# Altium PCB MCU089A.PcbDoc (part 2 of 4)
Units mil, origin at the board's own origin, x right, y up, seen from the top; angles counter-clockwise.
Board outline 2300 x 5500 mil, 4 copper layers (Top Signal, GND, PWR, Bottom Signal), stack 61.6 mil thick; 262 components, 208 nets, 964 pads, 377 vias.
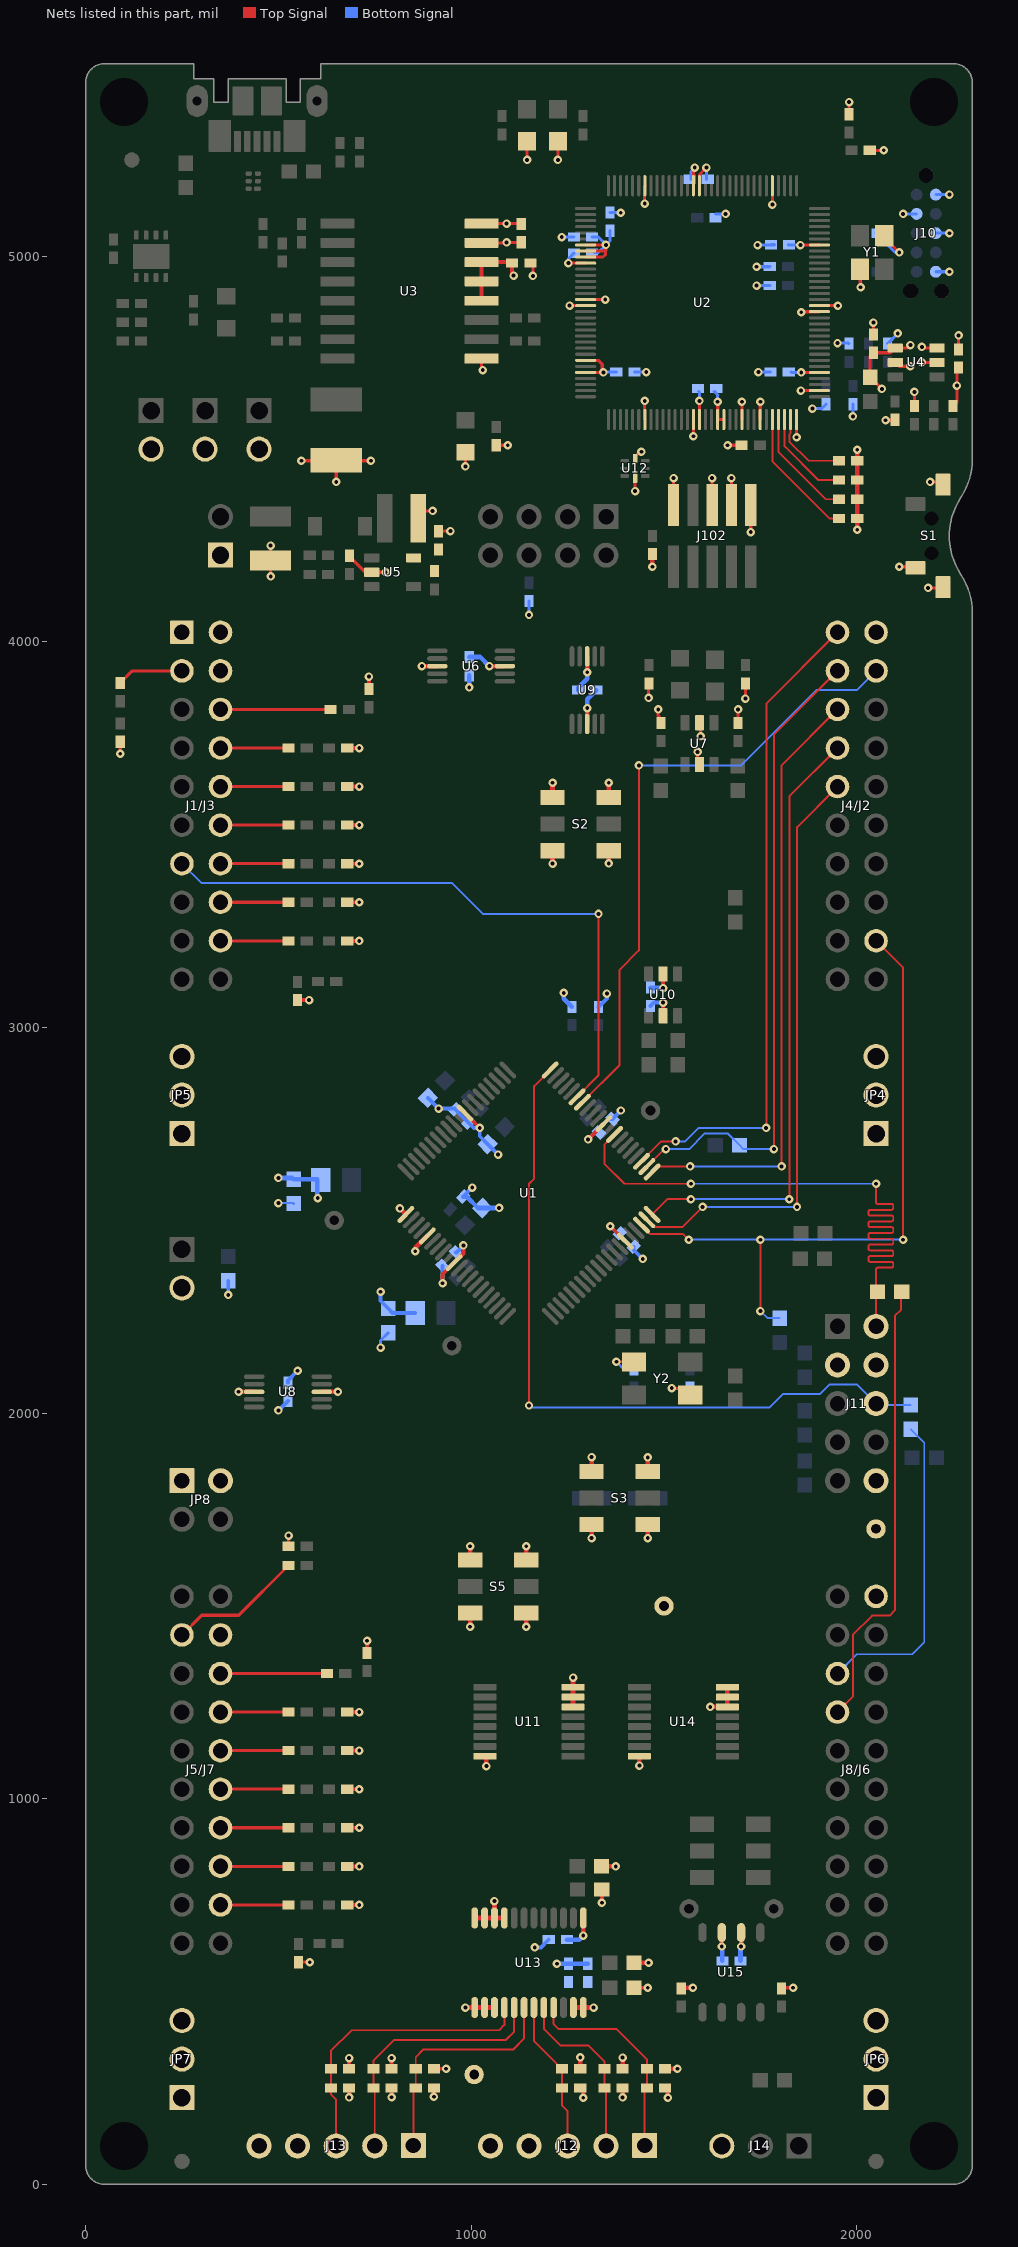
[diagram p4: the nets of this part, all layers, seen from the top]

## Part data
C1 C2 C6 C10 C11 C12 C13 C14 C17 C20 C21 C22 C23 C43 C44 C45 C46 C49 C64 C65 C74 C105 C106: library part CMP-0006629-2, "CAP, CERM, 0.1 uF, 10 V, +/- 10%, X7R, 0402", Cap_Case=0402, Manufacturer=MuRata, Supplier Part Number 1=GRM155R71A104KA01D-ND, TempCo=X7R, Tolerance_%=10%, Value1=Unknown, Value2=10V, ValueDisplayed=0.1uF
C3: library part CMP-0006404-2, "CAP, CERM, 820 pF, 25 V, +/- 5%, C0G/NP0, 0402", Cap_Case=0402, Manufacturer=MuRata, Supplier Part Number 1=GRM1555C1E821JA01D-ND, TempCo=C0G/NP0, Tolerance_%=5%, Value1=Unknown, Value2=25V, ValueDisplayed=820pF
C4: library part CMP-0064938-2, "CAP, CERM, 10 uF, 25 V,+/- 10%, X7R, 1210", Cap_Case=1210, Manufacturer="Wurth Elektronik", Supplier Part Number 1=732-7729-1-ND, TempCo=X7R, Tolerance_%=10%, Value1=Unknown, Value2=25V, ValueDisplayed=10uF
C5: library part CMP-0006220-2, "CAP, CERM, 4.7 uF, 6.3 V, +/- 20%, X5R, 0402", Cap_Case=0402, Manufacturer="Wurth Elektronik", Supplier Part Number 1=732-7485-1-ND, TempCo=X5R, Tolerance_%=20%, Value1=Unknown, Value2=6.3V, ValueDisplayed=4.7uF
C7 C8 C50 C51 C52 C53 C58: library part CMP-0006658-2, "CAP, CERM, 0.01 uF, 25 V, +/- 10%, X7R, 0402", Cap_Case=0402, Manufacturer=MuRata, Supplier Part Number 1=490-1312-1-ND, TempCo=X7R, Tolerance_%=10%, Value1=Unknown, Value2=25V, ValueDisplayed=0.01uF
C9 C18 C19: library part CMP-0007318-5, "CAP, CERM, 10 uF, 10 V, +/- 20%, X5R, 0603", Cap_Case=0603, Manufacturer=MuRata, TempCo=X5R, Tolerance_%=20%, Value1=Unknown, Value2=10V, ValueDisplayed=10uF
C15 C16: library part CMP-0007323-5, "CAP, CERM, 2.2 uF, 10 V, +/- 10%, X5R, 0603", Cap_Case=0603, Manufacturer=MuRata, Supplier Part Number 1=490-1545-1-ND, TempCo=X5R, Tolerance_%=10%, Value1=Unknown, Value2=10V, ValueDisplayed=2.2uF
C24: library part CMP-0007323-5, "CAP, CERM, 2.2 uF, 10 V, +/- 10%, X5R, 0603", Cap_Case=0603, Manufacturer=MuRata, Supplier Part Number 1=490-1545-1-ND, TempCo=X5R, Tolerance_%=10%, Value1=Unknown, Value2=10V
C25 C26 C27 C28 C29 C30 C31 C32 C33 C34 C35 C36 C37 C38 C39 C40: library part CMP-0006249-2, "CAP, CERM, 220 pF, 50 V, +/- 1%, C0G/NP0, 0402", Cap_Case=0402, Manufacturer=TDK, Supplier Part Number 1=445-7015-1-ND, TempCo=C0G/NP0, Tolerance_%=1%, Value1=Unknown, Value2=50V, ValueDisplayed=220pF
C41 C42 C102: library part CMP-0006216-2, "CAP, CERM, 15 pF, 50 V, +/- 5%, C0G/NP0, 0402", Cap_Case=0402, Manufacturer="Wurth Elektronik", Supplier Part Number 1=710-885012005056, TempCo=C0G/NP0, Tolerance_%=5%, Value1=Unknown, Value2=50V, ValueDisplayed=15pF
C47 C48: library part CMP-0006720-2, "CAP, CERM, 0.1 uF, 25 V, +/- 20%, X7R, 0402", Cap_Case=0402, Manufacturer="Taiyo Yuden", TempCo=X7R, Tolerance_%=20%, Value1=Unknown, Value2=25V, ValueDisplayed=0.1uF
C54 C55 C60 C66: library part CMP-0006623-2, "CAP, CERM, 0.1 uF, 6.3 V, +/- 10%, X7R, 0402", Cap_Case=0402, Manufacturer=MuRata, Supplier Part Number 1=GRM155R70J104KA01D-ND, TempCo=X7R, Tolerance_%=10%, Value1=Unknown, Value2=6.3V, ValueDisplayed=0.1uF
C56 C57 C61: library part CMP-0064924-2, "CAP, CERM, 1 uF, 10 V,+/- 20%, X5R, 0402", Cap_Case=0402, Manufacturer="Wurth Elektronik", Supplier Part Number 1=732-7489-1-ND, TempCo=X5R, Tolerance_%=20%, Value1=Unknown, Value2=10V, ValueDisplayed=1uF
C59 C100 C103: library part CMP-0006543-2, "CAP, CERM, 2.2 uF, 6.3 V, +/- 10%, X5R, 0402", Cap_Case=0402, Manufacturer=MuRata, Supplier Part Number 1=81-GRM155R60J225KE5D, TempCo=X5R, Tolerance_%=10%, Value1=Unknown, Value2=6.3V, ValueDisplayed=2.2uF
C62 C63: library part CMP-0006239-2, "CAP, CERM, 12 pF, 25 V, +/- 5%, C0G/NP0, AEC-Q200 Grade 1, 0402", Cap_Case=0402, Manufacturer=Kemet, Supplier Part Number 1=399-6829-1-ND, TempCo=C0G/NP0, Tolerance_%=5%, Value1=Unknown, Value2=25V, ValueDisplayed=12pF
C67 C68 C69 C70 C71 C72 C73: library part CMP-0006231-2, "CAP, CERM, 1000 pF, 50 V, +/- 10%, X7R, 0402", Cap_Case=0402, Manufacturer="Wurth Elektronik", Supplier Part Number 1=732-7556-1-ND, TempCo=X7R, Tolerance_%=10%, Value1=Unknown, Value2=50V, ValueDisplayed=1000pF
C101: library part CMP-0006688-2, "CAP, CERM, 3300 pF, 50 V, +/- 10%, X7R, 0402", Cap_Case=0402, Manufacturer=MuRata, Supplier Part Number 1=490-3248-1-ND, TempCo=X7R, Tolerance_%=10%, Value1=Unknown, Value2=50V, ValueDisplayed=3300pF
C104: library part CMP-0009297-2, "CAP, CERM, 0.01 uF, 1500 V, +/- 10%, X7R, 1812", Cap_Case=1812, Manufacturer=AVX, Supplier Part Number 1=478-4735-1-ND, TempCo=X7R, Tolerance_%=10%, Value1="0.05 ohm", Value2=1500V, ValueDisplayed=0.01uF
"CE Logo1": library part CMP-0074844-1
D1: library part CMP-0028360-2, "Diode, Schottky, 40 V, 1 A, SOD-123", Manufacturer="Diodes Inc.", Value1=1A, Value2=0.45V
FID1 FID2 FID3 FID4 FID5 FID6: library part CMP-0077181-1, "Fiducial mark.  There is nothing to buy or mount.", Manufacturer=N/A
J1/J3: library part CMP-0003837-4, "Receptacle, 2.54mm, 10x2, Tin, TH", Alternate Manufacturer="Major League Electronics", Alternate PartNumber=CRD-081413-A-G, Manufacturer=Samtec, Supplier Part Number 1=SAM1204-10-ND
J4/J2: library part CMP-0078266-4, "Receptacle, 2.54mm, 10x2, Tin, TH", Alternate Manufacturer="Major League Electronics", Alternate PartNumber=CRD-081413-A-G, Manufacturer=Samtec, Supplier Part Number 1=SAM1204-10-ND
J5/J7: library part CMP-0081070-3, "Receptacle, 2.54mm, 10x2, Tin, TH", Alternate Manufacturer="Major League Electronics", Alternate PartNumber=CRD-081413-A-G, Manufacturer=Samtec, Supplier Part Number 1=SAM1204-10-ND
J8/J6: library part CMP-0081071-3, "Receptacle, 2.54mm, 10x2, Tin, TH", Alternate Manufacturer="Major League Electronics", Alternate PartNumber=CRD-081413-A-G, Manufacturer=Samtec, Supplier Part Number 1=SAM1204-10-ND
J10: library part CMP-0075101-1, "Footprint for Tag-Connect TC2050 No-Legs cables", Manufacturer=Tag-Connect
J11: library part CMP-0075410-2, "Header, 100mil, 5x2, Gold, TH", Color=Black, Current_A=6.3A, Manufacturer=Samtec, Supplier Part Number 1=SAM1028-05-ND, Voltage_V=550V
J12 J13: library part CMP-0075411-1, "Header, 100mil, 5x1, Gold, TH", Color=Black, Current_A=6.3A, Manufacturer=Samtec, Supplier Part Number 1=SAM1029-05-ND, Voltage_V=550V
J14 JP4 JP5 JP6 JP7: library part CMP-0054796-1, "Header, 2.54 mm, 3x1, Gold, TH", Manufacturer="Wurth Elektronik", Supplier Part Number 1=732-5316-ND
J15 JP1 JP2 JP3 JP9: library part CMP-0054794-1, "Header, 2.54 mm, 2x1, Gold, TH", Manufacturer="Wurth Elektronik", Supplier Part Number 1=732-5315-ND
J101: library part CMP-0075408-2, "Header, 100mil, 4x2, Gold, TH", Color=Black, Current_A=6.3A, Manufacturer=Samtec, Supplier Part Number 1=SAM1028-04-ND, Voltage_V=550V
J102: library part CMP-0075670-2, "Header (Shrouded), 1.27mm, 5x2, Gold, SMT", Color=Black, Current_A=3.3A, Manufacturer=Samtec, Supplier Part Number 1=SAM8796-ND
JP8: library part CMP-0075404-1, "Header, 100mil, 2x2, Gold, TH", Color=Black, Current_A=6.3A, Manufacturer=Samtec, Supplier Part Number 1=SAM1028-02-ND, Voltage_V=550V
L1: library part CMP-0063754-1, "Inductor, Shielded Drum Core, Ferrite, 3.3 uH, 1.5 A, 0.085 ohm, SMD", Manufacturer="Wurth Elektronik", Supplier Part Number 1=732-2614-1-ND, Value1="0.085 ohm", Value2=1.5A, ValueDisplayed=3.3uH
L2: library part CMP-0003093-1, "Ferrite Bead, 60 ohm @ 100 MHz, 3 A, 0805", Manufacturer="Wurth Elektronik", Supplier Part Number 1=732-1612-1-ND, Value1="0.025 ohm", Value2=3A, ValueDisplayed="60 ohm"
L3: library part CMP-0003073-1, "Ferrite Bead, 220 ohm @ 100 MHz, 2 A, 0805", Manufacturer="Wurth Elektronik", Supplier Part Number 1=732-1614-1-ND, Value1="0.05 ohm", Value2=2A, ValueDisplayed="220 ohm"
L100 L101: library part CMP-0003183-2, "Ferrite Bead, 100 ohm @ 100 MHz, 0.5 A, 0603", Manufacturer="Wurth Elektronik", Supplier Part Number 1=732-1579-1-ND, Value1="0.15 ohm", Value2=0.5A, ValueDisplayed="100 ohm"
LED0 LED1 LED4: library part CMP-0002951-3, "LED, Red, SMD", Color=Red, Manufacturer="Wurth Elektronik", Power_TotalModule=72mW, Value1=0.072W, Value2=1.9V
LED2 LED3: library part CMP-0002889-2, "LED, Blue, SMD", Color=Blue, Manufacturer=Lite-On, Value1=W, Value2=3.3V
LED5: library part CMP-0002830-3, "LED, Green, SMD", Color=green, Manufacturer=Lite-On, Value1=W, Value2=2.1V
Logo1 Logo5: library part CMP-0074838-1, "Texas Instrument Corporate Signature"
Logo2: library part CMP-0861049-2, "INSTASPIN FOC LOGO"
Logo3: library part CMP-0074847-1, "FCC_disclaimer"
Logo4: library part CMP-0074769-1
M1 M2 M3 M4 M5 M6 M7 M8 M9: library part CMP-0003761-2, "Shunt, 2.54mm, Gold, Black", Manufacturer="Wurth Elektronik", Supplier Part Number 1=732-2678-ND
MH1 MH2 MH3 MH4: library part CMP-0078424-2, "PCB Mounting Hole, No Pad", Manufacturer=Any, PartNumber=N/A
R1 R2 R103 R104: library part CMP-0026197-2, "RES, 24.3, 1%, 0.063 W, AEC-Q200 Grade 0, 0402", Manufacturer=Vishay-Dale, Power_W=63mW, Supplier Part Number 1=541-24.3LCT-ND, TempCo="100 ppm/C", Tolerance_%=1%, Value2=0.063W, Value_Code=24R3, ValueDisplayed=24.3
R3 R28 R29 R105: library part CMP-0026962-3, "RES, 680, 5%, 0.063 W, AEC-Q200 Grade 0, 0402", Manufacturer=Vishay-Dale, Power_W=63mW, Supplier Part Number 1=541-680JCT-ND, TempCo="200 ppm/C", Tolerance_%=5%, Value2=0.063W, Value_Code=680R, ValueDisplayed=680
R4 R10 R11: library part CMP-0026890-5, "RES, 2.2 k, 5%, 0.063 W, AEC-Q200 Grade 0, 0402", Manufacturer=Vishay-Dale, Power_W=63mW, Supplier Part Number 1=541-2.2KJCT-ND, TempCo="200 ppm/C", Tolerance_%=5%, Value2=0.063W, Value_Code=2k20, ValueDisplayed=2.2k
R5: library part CMP-0026822-3, "RES, 0, 5%, 0.063 W, AEC-Q200 Grade 0, 0402", Manufacturer=Vishay-Dale, Power_W=63mW, Supplier Part Number 1=541-0.0JCT-ND, TempCo="200 ppm/C", Tolerance_%=5%, Value2=0.063W, Value_Code=0000, ValueDisplayed=0
R6 R48: library part CMP-0025769-4, "RES, 2.2 k, 5%, 0.1 W, AEC-Q200 Grade 0, 0603", Manufacturer=Vishay-Dale, Power_W=100mW, Supplier Part Number 1=541-2.2KGCT-ND, TempCo="200 ppm/C", Tolerance_%=5%, Value2=0.1W, Value_Code=2k20, ValueDisplayed=2.2k
R7: library part CMP-0026730-1, "RES, 30.1 k, 1%, 0.063 W, 0402", Manufacturer="Yageo America", Power_W=63mW, Supplier Part Number 1=311-30.1KLRCT-ND, TempCo="100 ppm/C", Tolerance_%=1%, Value2=0.063W, Value_Code=30k1, ValueDisplayed=30.1k
R8 R9 R65 R67 R78 R80: library part CMP-0026825-5, "RES, 10 k, 5%, 0.063 W, AEC-Q200 Grade 0, 0402", Manufacturer=Vishay-Dale, Power_W=63mW, Supplier Part Number 1=541-10KJCT-ND, TempCo="200 ppm/C", Tolerance_%=5%, Value2=0.063W, Value_Code=10k0, ValueDisplayed=10k
R12 R13 R14 R15 R16 R17 R18 R19 R20 R21 R22 R23 R24 R25 R26 R27: library part CMP-0026992-3, "RES, 0, 5%, 0.1 W, AEC-Q200 Grade 0, 0402", Manufacturer=Panasonic, Power_W=100mW, Supplier Part Number 1=P0.0JCT-ND, TempCo="600 ppm/C", Tolerance_%=5%, Value2=0.1W, Value_Code=0000, ValueDisplayed=0
R30 R31: library part CMP-0026826-2, "RES, 10 M, 5%, 0.063 W, AEC-Q200 Grade 0, 0402", Manufacturer=Vishay-Dale, Power_W=63mW, Supplier Part Number 1=541-10MJCT-ND, TempCo="200 ppm/C", Tolerance_%=5%, Value2=0.063W, Value_Code=10M0, ValueDisplayed=10M
R32 R33 R34 R35 R36 R37 R42 R43 R44 R45 R46 R47 R49 R50 R51 R52 R53 R54 R55 R56 R69 R71 R81: library part CMP-0025697-4, "RES, 0, 5%, 0.1 W, AEC-Q200 Grade 0, 0603", Manufacturer=Vishay-Dale, Power_W=100mW, Supplier Part Number 1=541-0.0GCT-ND, TempCo="200 ppm/C", Tolerance_%=5%, Value2=0.1W, Value_Code=0000, ValueDisplayed=0
R38 R39: library part CMP-0022746-5, "RES, 10.0 k, 1%, 0.1 W, 0603", Manufacturer=Yageo, Power_W=100mW, Supplier Part Number 1=311-10.0KHRCT-ND, TempCo="100 ppm/C", Tolerance_%=1%, Value2=0.1W, Value_Code=10k0, ValueDisplayed=10.0k
R40 R41 R58 R59 R60 R61 R72 R73 R74 R75 R76 R77: library part CMP-0026071-3, "RES, 1.00 k, 1%, 0.063 W, AEC-Q200 Grade 0, 0402", Manufacturer=Vishay-Dale, Power_W=63mW, Supplier Part Number 1=541-1.00KLCT-ND, TempCo="100 ppm/C", Tolerance_%=1%, Value2=0.063W, Value_Code=1k00, ValueDisplayed=1.00k
R57: library part CMP-0026918-5, "RES, 3.3 k, 5%, 0.063 W, AEC-Q200 Grade 0, 0402", Manufacturer=Vishay-Dale, Power_W=63mW, Supplier Part Number 1=541-3.3KJCT-ND, TempCo="200 ppm/C", Tolerance_%=5%, Value2=0.063W, Value_Code=3k30, ValueDisplayed=3.3k
R62 R66: library part CMP-0026824-3, "RES, 100, 5%, 0.063 W, AEC-Q200 Grade 0, 0402", Manufacturer=Vishay-Dale, Power_W=63mW, Supplier Part Number 1=541-100JCT-ND, TempCo="200 ppm/C", Tolerance_%=5%, Value2=0.063W, Value_Code=100R, ValueDisplayed=100
R63 R64: library part CMP-0026699-1, "RES, 470, 1%, 0.1 W, AEC-Q200 Grade 0, 0402", Manufacturer=Panasonic, Power_W=100mW, Supplier Part Number 1=P470LCT-ND, TempCo="100 ppm/C", Tolerance_%=1%, Value2=0.1W, Value_Code=470R, ValueDisplayed=470
R68: library part CMP-0026413-2, "RES, 4.87 k, 1%, 0.063 W, AEC-Q200 Grade 0, 0402", Manufacturer=Vishay-Dale, Power_W=63mW, Supplier Part Number 1=541-4.87KLCT-ND, TempCo="100 ppm/C", Tolerance_%=1%, Value2=0.063W, Value_Code=4k87, ValueDisplayed=4.87k
R70: library part CMP-0026946-3, "RES, 51, 5%, 0.063 W, AEC-Q200 Grade 0, 0402", Manufacturer=Vishay-Dale, Power_W=63mW, Supplier Part Number 1=541-51JCT-ND, TempCo="200 ppm/C", Tolerance_%=5%, Value2=0.063W, Value_Code=51R0, ValueDisplayed=51
R79: library part CMP-0022769-3, "RES, 120, 1%, 0.1 W, 0603", Manufacturer="Yageo America", Power_W=100mW, Supplier Part Number 1=311-120HRCT-ND, TempCo="200 ppm/C", Tolerance_%=1%, Value2=0.1W, Value_Code=120R, ValueDisplayed=120
R100: library part CMP-0026100-2, "RES, 1.00 M, 1%, 0.063 W, AEC-Q200 Grade 0, 0402", Manufacturer=Vishay-Dale, Power_W=63mW, Supplier Part Number 1=541-1.00MLCT-ND, TempCo="100 ppm/C", Tolerance_%=1%, Value2=0.063W, Value_Code=1M00, ValueDisplayed=1.00M
R101: library part CMP-0088102-2, "RES Thick Film SMD 51kΩ 1% 1/16W 0402 100ppm/K", Manufacturer=Vishay, Power_W=63mW, Tolerance_%=1%, ValueDisplayed=51k
R102: library part CMP-0078244-2, "RES, 30.0 k, 1%, 0.063 W, AEC-Q200 Grade 0, 0402", Manufacturer=Vishay-Dale, Power_W=63mW, Supplier Part Number 1=541-30.0KLCT-ND, TempCo="100 ppm/C", Tolerance_%=1%, Value2=0.063W, Value_Code=30k0, ValueDisplayed=30.0k
S1: library part CMP-0002328-1, "Switch, SPST, 0.05 A, 12 VDC, SMD", CurrentRating_mA=50A, Manufacturer=Diptronics
S2 S3 S5: library part CMP-0002233-1, "Switch, Dual SPDT,  2 Pos, 0.1A, 6VDC, SMD", CurrentRating_mA=100A, Manufacturer="Copal Electronics", Supplier Part Number 1=CASD20JCT-ND
S4: library part CMP-0002123-2, "SLIDE SWITCH DPDT  .1A, SMT", CurrentRating_mA=100A, Manufacturer="Copal Electronics", Supplier Part Number 1=CAS220JCT-ND
TP1 TP2 TP3 TP4 TP5 TP6 TP7 TP8: library part CMP-0078143-3, "TEST POINT.  No entry in BOM.", Manufacturer=N/A
U1: library part CMP-0089804-2, "32-bit MCU with 100 MHz, FPU, TMU, 128-KB flash, CLB 80-LQFP -40 to 125", Frequency_Fixed=100MHz, Manufacturer="Texas Instruments", Max Supply Voltage=3.63V, Min Supply Voltage=2.8V, Operating Temperature Range="-40°C to +125°C"
U2: library part CMP-0077953-1, "MSP432E401YTPDT, PDT0128A (TQFP-128)", Alternate Manufacturer="Texas Instruments", Alternate PartNumber=MSP432E401YTPDTR
U3: library part CMP-0074604-2, "Full/Low Speed 2.5 kV USB Digital Isolator, SOIC-16", Manufacturer="Analog Devices", Supplier Part Number 1=ADUM3160BRWZ-ND
U4: library part CMP-0067340-2, "High-Accuracy, Fixed-Threshold OV/UV Monitor, DDC0006A (SOT-23-T-6)", Alternate Manufacturer="Texas Instruments", Alternate PartNumber=TPS3702CX33DDCT
U5: library part CMP-0066119-1, "SIMPLE SWITCHER 2.7V to 5.5V, 2.1A Step-Up Regulator in SOT-23, DBV0005A (SOT-23-5)", Alternate Manufacturer="Texas Instruments", Alternate PartNumber=LMR62421XMFE/NOPB
U6 U8 U9: library part CMP-0067418-1, "DUAL 10-Ohm SPDT ANALOG SWITCH, DGS0010A (VSSOP-10)", Alternate Manufacturer="Texas Instruments", Alternate PartNumber=TS5A23157DGST
U7: library part CMP-0051789-2, "Dual Buffer/Driver with Open-Drain Output, DBV0006A, LARGE T&R", F @ Nom Voltage(Max)(Mhz)=150, Generic Part Number=SN74LVC2G07, ICC @ Nom Voltage(Max)(mA)=0.01, Manufacturer="Texas Instruments", Operating Temperature Range(C)="-40 to 125", Rating=Catalog, tpd @ Nom Voltage(Max)(ns)=8.6,4.4,3.7,2.9, Voltage(Nom)(V)=1.8,2.5,3.3,5
U10: library part CMP-0051910-1, "Dual Buffer Gate, DBV0006A, LARGE T&R", F @ Nom Voltage(Max)(Mhz)=150, Generic Part Number=SN74LVC2G34, ICC @ Nom Voltage(Max)(mA)=0.01, Manufacturer="Texas Instruments", Operating Temperature Range(C)="-40 to 125,-40 to 85", Rating=Catalog, tpd @ Nom Voltage(Max)(ns)=8.6,4.4,4.1,3.2, Voltage(Nom)(V)=1.8,2.5,3.3,5
U11 U14: library part CMP-0089841-1, "3 Circuit IC Switch 2:1 75Ohm 16-TSSOP", Digikey Part Number=296-3833-1-ND, Manufacturer="Texas Instruments", Max Supply Voltage=5.5V, Min Supply Voltage=2V, Mouser Part Number=595-SN74LV4053APWR, Nominal Supply Current=20uA, On State Resistance=100-225Ω, Operating Temperature Range="-40°C to +85°C"
U12: library part CMP-0043125-4, "Low-Capacitance 6-Channel +/-15 kV ESD Protection Array for High-Speed Data Interfaces, RSE0008A (UQFN-8)", Breakdown Voltage(Min)(V)=6, IO Capacitance(Typ)(pF)=1.6, IO Leakage Current(nA)=1, Manufacturer="Texas Instruments"
U13: library part CMP-0066458-2, "8-Bit Dual-Supply Bus Transceiver with Configurable Voltage-Level Shifting and Three-State Outputs, PW0024A (TSSOP-24)", Alternate Manufacturer="Texas Instruments", Operating Temperature Range="-40 to 85 C", Rating=Catalog
U15: library part CMP-0033355-1, "3.3V CAN Transceiver with Sleep Mode, 6 mA, -40 to 125 degC, 8-pin SOIC (D), Green (RoHS & no Sb/Br)", Bus Fault Voltage(V)=+/-30, Drivers Per Package=1, Low Power Mode=Sleep, Manufacturer="Texas Instruments", Rating=Catalog, Supply Voltage(s)(V)=3.3
U100: library part CMP-0043115-3, "4-Channel ESD Protection Array for High-Speed Data Interfaces, DRY0006A (USON-6)", Breakdown Voltage(Min)(V)=6, IO Capacitance(Typ)(pF)=1.6, IO Leakage Current(nA)=1, Manufacturer="Texas Instruments", Operating Temperature Range="-40 to 85 C", Rating=Catalog
U101: library part CMP-0036402-3, "Single Output High PSRR LDO, 1 A, Adjustable 1.2 to 5.5 V Output, 2.7 to 5.5 V Input, 8-pin SON (DRB), -40 to 125 degC, Green (RoHS & no Sb/Br)", Manufacturer="Texas Instruments"
USB101: library part CMP-0055311-1, "Receptacle, USB 2.0, Micro B, 5 Position, R/A, SMT", Color=Black, Current_A=1.8A, Manufacturer=Molex, Supplier Part Number 1=WM11263CT-ND, Voltage_V=30V
Y1: library part CMP-0004635-3, "Crystal, 16 MHz, 8pF, SMD", Frequency_Fixed=16MHz, Frequency Stability=+/-30ppm, Manufacturer=NDK, Supplier Part Number 1=644-1157-1-ND
Y2: library part CMP-0080365-2, "Crystal, 20 MHz, 25 ppm, 18 pF, SMD", Frequency_Fixed=20MHz, Frequency Stability="30 ppm", Frequency Tolerance="25 ppm", Load Capacitance="18 pF", Manufacturer="ECS Inc.", Supplier Part Number 1=XC2693CT-ND
ZZ1: library part CMP-0077236-1
ZZ2: library part CMP-0077237-1
ZZ3: library part CMP-0077238-1

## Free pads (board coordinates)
  rrect9% 41.73x57.87 on Top Paste: 9(145.2,5000) 9(194.8,5000)

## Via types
v1: diameter 22, hole 10, Top Signal to Bottom Signal, tented both sides, 377 vias

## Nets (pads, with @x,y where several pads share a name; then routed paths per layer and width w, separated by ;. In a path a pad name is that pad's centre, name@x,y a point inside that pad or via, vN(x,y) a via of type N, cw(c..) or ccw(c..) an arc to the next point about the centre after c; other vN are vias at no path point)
+3V3: C1.2 C2.2 C5.1 C6.2 C16.1 C18.1 C43.1 C44.2 C45.1 C46.2 C49.2 C51.1 C52.1 C53.1 C54.1 C55.1 C56.1 C57.1 C58.1 C64.1 C74.2 J1/J3.1 J10.1 J11.10 J102.1 JP2.2 JP4.1 JP6.1 JP8.1 L1.1 L2.2 L3.1 R3.2 R4.2 R6.2 R8.2 R10.2 R11.2 R28.2 R29.2 R30.2 R31.2 R47.2 R48.2 R57.2 R58.2 R59.2 R60.2 R61.2 R65.2 R70.2 R78.2 S2.1 S2.4 S3.3 S3.6 S5.3 S5.6 TP4.1 U2.7 U2.8 U2.9 U2.16 U2.26 U2.28 U2.39 U2.47 U2.51 U2.52 U2.69 U2.79 U2.90 U2.101 U2.113 U2.122 U3.12 U3.13 U3.14 U3.16 U4.3 U4.4 U4.5 U5.5 U6.8 U7.5 U8.8 U9.8 U10.5 U11.16 U12.8 U13.1 U14.16 U15.3 | length 3763
  Top Signal w8: L1.1@860.44,4318.04 L1.1@862.78,4320.38 882.4,4340 v1(900,4340) ; U3.16@1027.01,5085 C1.2@1135,5085 ; R3.2@1065,4510.04 v1(1095,4510.11) ; U2.28@1296.85,4698.9 1296.95,4699 v1(1343,4699) ; U2.26@1296.85,4730.39 1329.61,4730.39 1340,4720 v1@1340,4700 ; U2.16@1296.85,4887.87 v1(1347.87,4887.87) ; U2.9@1296.85,4998.11 1341.75,4998.11 1347.86,5004.22 1347.86,5013.86 ; U2.8@1296.85,5013.86 1347.86,5013.86 ; U2.7@1296.85,5029.61 1349,5029.61 1349,5015 1347.86,5013.86 ; v1(1425,4391.38) U12.8@1425,4424.41 ; v1(1450,4625) 1450,4577.24 U2.39@1450.39,4576.85 ; v1(1450,5137) 1450,5182.76 U2.122@1450.39,5183.15 ; v1(1460,3855) R28.2@1460,3883.57 ; R28.2@1462.04,3891.53 R28.2@1460,3889.49 ; v1(1485,3825) 1485,3808.57 1492.04,3801.53 R30.2@1492.04,3790.15 R30.2@1491.35,3790.84 ; v1(1576.38,4533.62) U2.47@1576.38,4576.85 ; U7.5@1592.04,3790.66 1595,3787.7 v1(1595,3755) ; U2.113@1592.13,5183.15 1592.13,5212.13 v1(1610,5230) ; v1(1639,4623) 1639,4619.74 1639.37,4619.37 1639.37,4576.85 U2.52@1654.78,4576.85 ; R31.2@1692.04,3790.15 v1(1692.04,3825) ; v1(1711.41,3853.35) 1711.41,3881.49 1717.04,3887.12 R29.2@1711.41,3892.75 ; v1(1725,4285) J102.1@1725,4355.12 ; v1(1781,5134) 1781,5183.05 U2.101@1781.1,5183.15 ; v1(1854,5029) 1901.76,5029 1902.76,5030 U2.90@1903.15,5029.61 ; v1@1855,4855 1856.38,4856.38 U2.79@1903.15,4856.38 ; v1(1856,4699) 1861,4699 1861.1,4698.9 U2.69@1903.15,4698.9 ; v1(2065,4656.22) R6.2@2034.61,4686.61 2034.61,4741.38 C44.2@2043.23,4750 2087.48,4750 U4.4@2099.88,4762.4 2131.42,4762.4 v1(2139.02,4770) ; U4.5@2099.88,4725 2109.88,4715 v1(2139.02,4715) ; R4.2@2149.61,4612 v1(2149.61,4648.38) ; v1(2169.02,4765) 2173.21,4765 2176.21,4762 2176.61,4762.4 U4.3@2208.15,4762.4 ; C6.2@2264.02,4758.62 v1(2264.02,4795) ; R28.2@1460,3883.57 1457.04,3886.53 R28.2@1460,3889.49 ; R28.2@1460,3883.57 R28.2@1460,3889.49
  Top Signal w10: U3.12@1027.01,4885 U3.13@1027.01,4935 U3.14@1027.01,4985 1103.74,4985 C2.2@1106.38,4982.36 1106.38,4953.62 v1(1110,4950) ; v1(1497.6,3102.6) U10.5@1497.6,3138.76
  Top Signal w12: U8.8@612.6,2055.5 v1(654.5,2055.5) ; S5.6@997.34,1619.4 v1(997.34,1655) ; U11.16@1035.83,1110.43 1039.43,1106.83 v1(1039.43,1085) ; v1(1047.34,3937.39) U6.8@1087.57,3937.39 ; S5.3@1143.01,1619.4 v1(1143.01,1655) ; S2.1@1210.98,3596.53 v1(1210.98,3635) ; v1(1290.75,645.46) U13.1@1290.75,691.14 ; v1(1300.9,3921.5) U9.8@1300.9,3962.6 ; S3.6@1312.28,1848.9 v1(1312.28,1886.4) ; R47.2@1338.35,825 v1(1375,825) ; S2.4@1356.65,3596.53 v1(1356.65,3635) ; R48.2@1422.24,575 v1(1460,575) ; v1(1436.21,1086.21) U14.16@1436.21,1110.43 ; S3.3@1457.95,1848.9 v1(1457.95,1885.49) ; v1(1470,4195) R57.2@1470,4227.69 ; R78.2@1544.88,508.62 1546.26,510 v1(1575,510) ; v1(1650,617.1) U15.3@1650,653.35 ; v1(2001.1,4291.1) R61.2@2001.1,4320 R60.2@2001.1,4370 R59.2@2001.1,4420 R58.2@2001.1,4470 v1(2001.1,4498.5)
  Bottom Signal w8: v1(1150,4070) R10.2@1150,4106.38 ; C58.1@1313.62,5050 1330,5050 1350,5030 1360,5040 C56.1@1360,5066.38 ; C57.1@1320,5010 1330,5010 v1(1349.61,5029.61) ; v1@1340,4700 C55.1@1376.38,4700 ; C51.1@1610,5200 v1(1610,5230) ; C54.1@1630,4650 1640,4640 1639,4639 v1(1639,4623) ; C52.1@1823,5030 1824,5029 v1(1854,5029) 1859,5029 1860,5030 v1@1854,5030 ; C53.1@1830,4700 1831,4699 v1(1856,4699) ; v1(1885,4605) 1908.62,4605 R70.2@1920,4616.38 ; v1(1950,4775) 1978.62,4775 R65.2@1980,4773.62 ; J10.1@2205,5160 v1(2240,5160)
  Bottom Signal w10: C45.1@525,2079.12 525,2085 v1(550,2110) ; v1(765,2314.88) 765,2291.5 C18.1@785,2271.5 796.5,2260 L3.1@855,2260
  Bottom Signal w12: v1(500,2610) 536.5,2610 C16.1@540,2606.5 600.55,2606.5 600.55,2559.45 v1(602.05,2557.95) ; C43.1@995,3961.01 1023.72,3961.01 v1(1047.34,3937.39) ; v1(1240,3090) 1240,3074.68 R11.2@1261.06,3053.62 ; C64.1@1248.62,635.05 1280.34,635.05 v1(1290.75,645.46) ; C46.2@1277.28,3875 1277.28,3881.53 1300.9,3905.15 v1(1300.9,3921.5) ; C49.2@1465,3103.62 1466.02,3102.6 v1(1497.6,3102.6) ; v1(1650,617.1) 1651.38,615.73 C74.2@1651.38,580
  other v1: 1856,4855 1092,5085
+5V0: C65.2 C67.1 J1/J3.21 J12.4 J13.4 JP3.2 JP5.1 JP7.1 JP8.2 JP9.1 R62.1 R72.2 R73.2 R74.2 R75.2 R76.2 R77.2 TP5.1 U13.23 U13.24 | length 234.3
  Top Signal w8: R62.1@1980,5368.62 v1(1980,5400)
  Top Signal w12: v1(683.62,225.99) R77.2@683.62,250 ; v1(793.62,226.1) R76.2@793.62,250 ; v1(903.62,227.36) R75.2@903.62,250 ; U13.23@1265.16,458.86 U13.24@1290.75,458.86 v1(1317.29,458.86) ; R74.2@1282.87,250 1290.75,242.13 v1(1290.75,225) ; v1(1392.87,225.99) R73.2@1392.87,250 ; R72.2@1502.87,250 1510,242.87 v1(1510,225)
ADCINA0/C15: J5/J7.69 R12.1 | length 176.4
  Top Signal w8: J5/J7.69@350,725 R12.1@526.38,725
ADCINA1: J5/J7.42 R13.1 | length 350.9
  Top Signal w8: J5/J7.42@250,1425 301.1,1476.1 397.48,1476.1 R13.1@526.38,1605
ADCINA2/C9: J1/J3.25 R14.1 | length 176.4
  Top Signal w8: J1/J3.25@350,3625 R14.1@526.38,3625
ADCINA3/C5: J1/J3.24 R15.1 | length 176.4
  Top Signal w8: J1/J3.24@350,3725 R15.1@526.38,3725
ADCINA4/C14: J5/J7.66 R16.1 | length 176.4
  Top Signal w8: J5/J7.66@350,1025 R16.1@526.38,1025
ADCINA5/C2: J5/J7.63 R17.1 | length 276.4
  Top Signal w8: J5/J7.63@350,1325 R17.1@626.38,1325
ADCINA6: J1/J3.23 R18.1 | length 285.7
  Top Signal w8: J1/J3.23@350,3825 R18.1@635.68,3825
ADCINA7/C3: J5/J7.64 R19.1 | length 176.4
  Top Signal w8: J5/J7.64@350,1225 R19.1@526.38,1225
ADCINA8/C11: J5/J7.65 R20.1 | length 176.4
  Top Signal w8: J5/J7.65@350,1125 R20.1@526.38,1125
ADCINA9/C8: J5/J7.67 R21.1 | length 176.4
  Top Signal w8: J5/J7.67@350,925 R21.1@526.38,925
ADCINA10/C10: J5/J7.68 R22.1 | length 176.4
  Top Signal w8: J5/J7.68@350,825 R22.1@526.38,825
ADCINA11/C0: J1/J3.28 R23.1 | length 176.4
  Top Signal w8: J1/J3.28@350,3325 R23.1@526.38,3325
ADCINA12/C1: J1/J3.29 R24.1 | length 176.4
  Top Signal w8: J1/J3.29@350,3225 R24.1@526.38,3225
ADCINA14/C4: J1/J3.27 R25.1 | length 176.4
  Top Signal w8: J1/J3.27@350,3425 R25.1@526.38,3425
ADCINA15/C7: J1/J3.26 R26.1 | length 176.4
  Top Signal w8: J1/J3.26@350,3525 R26.1@526.38,3525
ADCINC6: J1/J3.2 R27.1 | length 173
  Top Signal w8: R27.1@90,3893.62 121.38,3925 J1/J3.2@250,3925
DEBUG_ID4: R58.1 U2.63 | length 207.4
  Top Signal w5: U2.63@1828.35,4576.85 1828.35,4541.51 1825.5,4538.66 1825.5,4519.5 1875,4470 R58.1@1953.86,4470
DEBUG_ID5: R59.1 U2.62 | length 246.9
  Top Signal w5: U2.62@1812.6,4576.85 1812.6,4507.4 1900,4420 R59.1@1953.86,4420
DEBUG_ID6: R60.1 U2.61 | length 291.7
  Top Signal w5: U2.61@1796.85,4576.85 1796.85,4493.15 1920,4370 R60.1@1953.86,4370
DEBUG_ID7: R61.1 U2.60 | length 342.4
  Top Signal w5: U2.60@1781.1,4576.85 1781.1,4468.9 1930,4320 R61.1@1953.86,4320
EQEP1A: C68.1 J12.1 R72.1 U13.21 | length 548.4
  Top Signal w5: U13.21@1213.98,458.86 1213.98,415.59 1225.95,403.61 1376.39,403.61 1455.63,324.37 C68.1@1455.63,300 R72.1@1455.63,250 1450,244.37 J12.1@1450,101
EQEP1B: C69.1 J12.2 R73.1 U13.20 | length 468.6
  Top Signal w5: U13.20@1188.39,458.86 1188.39,403.61 1232,360 1305,360 1345.63,319.37 C69.1@1345.63,300 R73.1@1345.63,250 1350,245.63 J12.2@1350,100
EQEP1I: C70.1 J12.3 R74.1 U13.19 | length 395.3
  Top Signal w5: U13.19@1162.8,458.86 1162.8,372.2 1235,300 C70.1@1235.63,300 R74.1@1235.63,250 1235.63,204.37 1250,190 J12.3@1250,100
EQEP2A: C71.1 J13.1 R75.1 U13.18 | length 613
  Top Signal w5: J13.1@850,101 850,243.62 R75.1@856.38,250 C71.1@856.38,300 856.38,330.17 876.21,350 1108.62,350 1137.2,378.58 U13.18@1137.2,458.86
EQEP2B: C72.1 J13.2 R76.1 U13.17 | length 681.7
  Top Signal w5: J13.2@750,100 750,246.38 R76.1@746.38,250 C72.1@746.38,300 746.38,321.38 800,375 1090.37,375 1111.61,396.25 U13.17@1111.61,458.86
EQEP2I: C73.1 J13.3 R77.1 U13.16 | length 774.7
  Top Signal w5: J13.3@650,100 650,220 636.38,233.62 R77.1@636.38,250 C73.1@636.38,300 636.38,346.38 690,400 1072.27,400 1086.02,413.75 U13.16@1086.02,458.86
GND: C1.1 C2.1 C4.2 C5.2 C6.1 C7.2 C8.2 C9.1 C10.2 C11.2 C12.2 C13.2 C14.1 C15.2 C16.2 C17.1 C18.2 C19.2 C20.1 C21.1 C22.1 C23.1 C24.2 C25.2 C26.2 C27.2 C28.2 C29.2 C30.2 C31.2 C32.2 C33.2 C34.2 C35.2 C36.2 C37.2 C38.2 C39.2 C40.2 C41.2 C42.2 C43.2 C44.1 C45.2 C46.1 C47.2 C48.2 C49.1 C50.2 C51.2 C52.2 C53.2 C54.2 C55.2 C56.2 C57.2 C58.2 C59.2 C60.2 C61.2 C62.2 C63.2 C64.2 C65.1 C66.2 C67.2 C68.2 C69.2 C70.2 C71.2 C72.2 C73.2 C74.1 C104.1 J1/J3.22 J4/J2.20 J5/J7.62 J8/J6.60 J10.3 J10.5 J10.9 J11.3 J11.4 J12.5 J13.5 J14.3 J15.2 J102.3 J102.5 J102.9 JP1.2 JP4.2 JP4.3 JP5.2 JP5.3 JP6.2 JP6.3 JP7.2 JP7.3 LED1.1 LED2.2 LED3.2 R9.1 R52.1 R53.2 R67.1 R68.1 R80.1 S1.1 S1.2 S1.3 S2.3 S2.6 S3.1 S3.4 S5.1 S5.4 TP6.1 U1.9 U1.21 U1.25 U1.30 U1.55 U1.70 U2.10 U2.17 U2.48 U2.55 U2.58 U2.64 U2.66 U2.80 U2.114 U3.9 U3.15 U4.2 U5.2 U6.3 U7.2 U8.3 U9.3 U10.2 U11.6 U11.7 U11.8 U12.4 U13.9 U13.10 U13.11 U13.12 U13.13 U13.14 U13.15 U14.6 U14.7 U14.8 U15.2 Y1.2 Y1.4 Y2.2 Y2.4 | length 5980
  Top Signal w6: v1(1376.69,2133.31) Y2.4@1422.17,2133.31 ; v1(1520,2065) 1549.53,2065 Y2.2@1567.83,2046.69
  Top Signal w8: v1(480,4250) C4.2@480,4211.45 480.19,4211.26 v1(480.19,4170) ; C33.2@526.38,1655 v1(526.38,1682.79) ; C47.2@551.91,576.38 v1(581.36,576.38) ; R9.1@685,4223.62 685,4221.28 725.51,4180.77 U5.2@742.33,4180.77 v1(778.47,4180.77) ; C5.2@915,4287.24 938.62,4287.24 939,4287.62 v1(946,4287.62) ; v1(985,4455.11) LED1.1@985,4492.32 ; v1@1027.01,4712.99 U3.9@1027.01,4735 ; U3.15@1027.01,5035 1090,5035 1091.38,5036.38 C1.1@1128.38,5036.38 ; C1.1@1130,5036.38 C1.1@1128.38,5036.38 ; C1.1@1130,5038 C1.1@1128.38,5036.38 ; v1(1145,5250) LED2.2@1145,5298.66 ; C2.1@1153.62,4982.36 1160,4975.98 v1(1160,4949.37) ; v1(1225,5250) LED3.2@1225,5298.66 ; v1(1252.36,4982.36) U2.10@1296.85,4982.36 ; v1(1255.13,4872.13) U2.17@1296.85,4872.13 ; U12.4@1425,4475.59 1425,4480 1438.2,4493.2 v1(1441.59,4493.2) ; J102.9@1525,4355.12 v1(1525,4425) ; U2.114@1576.38,5183.15 1576.38,5226.38 v1(1580,5230) ; v1(1587.04,3715) 1587.04,3686.53 U7.2@1592.04,3681.53 ; v1(1592,4625) 1592,4618 1592.13,4617.87 U2.48@1592.13,4576.85 ; J102.5@1625,4355.12 v1(1625,4425) ; v1(1665,4510.11) R68.1@1701.38,4510.11 ; J102.3@1675,4355.12 v1(1675,4425) ; v1@1700,4625 v1(1702,4623) 1702.36,4622.64 U2.55@1702.36,4576.85 ; U2.58@1749.61,4576.85 1749.61,4624.61 v1@1750,4625 ; v1(1844,4531) 1844,4540.81 1844.09,4540.91 U2.64@1844.09,4576.85 ; v1@1851.65,4651.65 v1@1855,4651.65 ; v1@1855,4650 1856.65,4651.65 U2.66@1903.15,4651.65 ; v1(1855,4652) v1@1861.31,4652 ; U2.80@1903.15,4872.13 1947.87,4872.13 v1@1950,4870 ; v1@1950,4872 v1(1951,4872) ; Y1.4@2008.5,4966.69 2008.5,4931.5 2010,4930 v1(2010,4920) ; C50.2@2033.62,5275 v1(2070,5275) ; C44.1@2043.23,4797.24 v1(2043.23,4828.23) ; Y1.2@2070,5050 v1(2110,5010) ; v1(2074.61,4575) 2097.64,4575 C8.2@2099.02,4576.38 C8.2@2102.64,4580 ; v1(2110,4195) 2150,4195 S1.3@2150,4185 ; v1(2169.02,4725) U4.2@2208.15,4725 ; v1(2185,4140) S1.1@2225,4140 ; v1(2190,4415) 2216.18,4415 S1.2@2223.31,4407.87 ; C7.2@2249.61,4612 2259.61,4622 v1(2259.61,4665) 2259.61,4706.97 C6.1@2264.02,4711.38
  Top Signal w10: v1(90,3710) C40.2@90,3741.38 ; C48.2@549.19,3071.38 v1(579.62,3071.38) ; v1(560,4470) 649.27,4470 C104.1@650,4469.27 ; v1(650,4415) C104.1@650,4469.27 ; C25.2@678.62,725 v1(710,725) ; C30.2@678.62,825 v1(710,825) ; C37.2@678.62,925 v1(710,925) ; C27.2@678.62,1025 v1(710,1025) ; C29.2@678.62,1125 v1(710,1125) ; C36.2@678.62,1225 v1(710,1225) ; C31.2@678.62,3225 v1(710,3225) ; C38.2@678.62,3325 v1(710,3325) ; C39.2@678.62,3425 v1(710,3425) ; C32.2@678.62,3525 v1(710,3525) ; C26.2@678.62,3625 v1(710,3625) ; C34.2@678.62,3725 v1(710,3725) ; C73.2@683.62,300 v1(683.62,327.69) ; C35.2@730,1378.62 v1(730,1410) ; C28.2@735,3877.93 v1(735,3910) ; v1(740,4470) 650.73,4470 C104.1@650,4469.27 ; C72.2@793.62,300 v1(793.62,327.58) ; C71.2@903.62,300 v1(935,300) ; v1(925.96,2337) 925.96,2360.45 U1.30@955.81,2390.29 980,2414.49 v1(980,2435) ; U1.9@983.64,2778.64 v1(1022.29,2740) ; v1(1303.35,2710) U1.70@1344.16,2750.81 ; v1(1338.9,730.54) R52.1@1338.9,765 ; v1(1360.81,2485) U1.55@1399.84,2445.97 ; R53.2@1422.24,510 v1(1457.95,510) ; U10.2@1497.6,3030.49 v1(1497.6,3065) ; R80.1@1805,508.62 1806.38,510 v1(1835,510)
  Top Signal w12: v1(397,2055.5) U8.3@437.4,2055.5 ; v1(815.09,2531) U1.21@830.53,2515.57 ; v1(855,2420) 855,2428.68 U1.25@886.21,2459.89 ; v1(872.34,3937.39) U6.3@912.38,3937.39 ; v1(985,458.86) U13.13@1009.25,458.86 U13.14@1034.84,458.86 U13.15@1060.43,458.86 ; v1(997.34,1446.35) S5.4@997.34,1481.6 ; U13.12@1009.25,691.14 U13.11@1034.84,691.14 U13.10@1060.43,691.14 U13.9@1086.02,691.14 ; U13.10@1060.43,691.28 v1(1060.43,735) ; v1(1143.01,1446.41) S5.1@1143.01,1481.6 ; v1(1210.98,3425.23) S2.3@1210.98,3458.73 ; U11.6@1264.17,1238.39 U11.7@1264.17,1263.98 U11.8@1264.17,1289.57 v1(1264.17,1314.33) ; C70.2@1282.87,300 v1(1282.87,329.71) ; U9.3@1300.9,3787.4 v1(1300.9,3828.5) ; v1(1312.28,1676.34) S3.4@1312.28,1711.1 ; v1(1356.65,3425.9) S2.6@1356.65,3458.73 ; C69.2@1392.87,300 v1(1392.87,328.84) ; v1(1457.95,1676.34) S3.1@1457.95,1711.1 ; C68.2@1502.87,300 v1(1535,300) ; v1(1620,1238.39) U14.6@1664.56,1238.39 U14.7@1664.56,1263.98 U14.8@1664.56,1289.57 ; v1(1700,617.1) U15.2@1700,653.35
  Bottom Signal w6: v1(500,2545) 538.5,2545 C16.2@540,2543.5 ; v1(1376.69,2133.31) 1396.38,2113.62 C41.2@1422.17,2113.62 ; v1(1520,2065) 1566.46,2065 C42.2@1567.83,2066.38
  Bottom Signal w8: v1(370.07,2306.84) C24.2@370.07,2343.5 ; v1(765,2170) 765,2188.5 C18.2@785,2208.5 ; v1(1235,5050) C58.2@1266.38,5050 ; v1(1252.36,4982.36) 1252.36,4993.98 C57.2@1266.38,5008 ; C56.2@1360,5113.62 1376.38,5113.62 1377,5113 v1(1388,5113) ; C55.2@1423.62,4700 v1(1454,4700) ; C51.2@1570,5200 1570,5220 v1(1580,5230) ; C54.2@1590,4650 1592,4648 v1(1592,4625) ; C61.2@1633.62,5110 v1(1660,5110) ; v1(1740,4924) C60.2@1774.38,4924 ; v1(1740,4973) 1773.38,4973 C59.2@1774.38,4974 ; v1(1743,5029) 1776.38,5029 C52.2@1777.38,5030 C52.2@1786.38,5030 ; v1(1745,4700) C53.2@1776.38,4700 ; v1(1990,4585) C66.2@1990,4616.38 ; v1(2010,4920) C63.2@2010,4960 ; C62.2@2050,5060 2100,5010 v1(2110,5010) ; R67.1@2080,4773.62 v1(2106.38,4800) ; v1(2120,5110) J10.9@2155,5110 ; J10.5@2205,4960 v1(2240,4960) ; J10.3@2205,5060 v1(2240,5060)
  Bottom Signal w10: v1(500,2007.5) 500.62,2007.5 C45.2@525,2031.88 ; C9.1@887.73,2817.73 v1(915.46,2790) 956.59,2790 C13.2@958.3,2788.3 C20.1@993.3,2753.3 1006.59,2740 v1(1022.29,2740) 1022.29,2718.17 C19.2@1042.73,2697.73 v1(1069.68,2670.77) ; v1(925.96,2337) C21.1@925.96,2381.7 ; C12.2@960.96,2416.7 961.7,2416.7 v1(980,2435) ; C14.1@979.37,2561.7 v1(1002.67,2585) ; v1(1165,614.95) 1181.27,614.95 C64.2@1201.38,635.05 ; v1(1303.35,2710) 1356.65,2763.3 C10.2@1366.7,2763.3 v1(1388.41,2785) ; C17.1@1330.24,3053.62 1351.85,3075.23 v1(1351.85,3088.15) ; v1(1360.81,2485) 1414.1,2431.7 C11.2@1421.7,2431.7 1421.7,2423.3 v1(1445,2400) ; C49.1@1465,3056.38 1473.62,3065 v1(1497.6,3065)
  Bottom Signal w12: C14.1@979.37,2561.7 988.3,2561.7 1017.73,2532.27 C15.2@1028.85,2532.27 v1(1072.27,2532.27) ; v1(995,3882.34) C43.2@995,3913.77 ; v1(1222.24,572.24) C67.2@1252.36,572.24 C65.1@1302.4,572.24 ; v1(1300.9,3828.5) 1300.9,3851.38 C46.1@1324.52,3875 ; C74.1@1698.62,580 1698.62,615.73 v1(1700,617.1)
  other v1: 1750,4623 1030,4705 1092,5036
GPIO0: J4/J2.40 U1.63 | length 1720.8
  Top Signal w5: U1.63@1441.59,2653.37 1493.22,2705 v1(1530,2705) ; v1@1765.35,2740 1765.35,3840.35 J4/J2.40@1950,4025
  Bottom Signal w5: v1(1530,2705) 1555,2705 1590,2740 v1(1765,2740)
GPIO1: J4/J2.39 R56.2 U1.62 | length 1689.8
  Top Signal w5: U1.62@1455.51,2639.45 1501.06,2685 v1(1505,2685) ; v1(1785,2685) 1785,3760 J4/J2.39@1950,3925
  Bottom Signal w5: v1(1505,2685) 1565,2685 1605,2725 1666.05,2725 R56.2@1696.05,2695 1706.05,2685 v1(1785,2685)
GPIO2: J4/J2.38 U1.61 | length 1586.6
  Top Signal w5: U1.61@1469.43,2625.53 1483.9,2640 v1(1567.83,2640) ; v1(1805,2640) 1805,3680 J4/J2.38@1950,3825
  Bottom Signal w5: v1(1567.83,2640) 1775,2640 v1(1805,2640)
GPIO3: J4/J2.37 U1.60 | length 1593.7
  Top Signal w5: U1.60@1469.43,2515.57 1508.86,2555 v1(1570,2555) ; v1(1825,2555) 1825,3600 J4/J2.37@1950,3725
  Bottom Signal w5: v1(1570,2555) v1(1825,2555)
GPIO4: J4/J2.36 U1.59 | length 1552.7
  Top Signal w5: U1.59@1455.51,2501.65 1474.66,2482.5 1547.5,2482.5 v1(1600,2535) ; v1(1845,2535) 1845,3520 J4/J2.36@1950,3625
  Bottom Signal w5: v1(1600,2535) 1840,2535 v1(1845,2535)
GPIO5: J4/J2.19 U1.74 | length 1650.7
  Top Signal w5: U1.74@1288.48,2806.48 1385,2903 1385,3150 1435,3200 v1(1435,3680)
  Bottom Signal w5: v1(1435,3680) 1700,3680 1895,3875 2000,3875 J4/J2.19@2050,3925
GPIO6_BP: J8/J6.78 R49.2 | length 825.3
  Bottom Signal w5: J8/J6.78@1950,1325 2000,1375 2143.5,1375 2175,1406.5 2175,1923.5 R49.2@2140,1958.5
GPIO6_FSITXD0: J11.6 R49.1 U1.80 | length 1934.8
  Top Signal w5: v1(1150,2020) 1150,2595 1163.21,2608.21 1163.21,2848.24 U1.80@1204.96,2890
  Bottom Signal w5: v1(1150,2020) 1150,2015 1774.38,2015 1809.38,2050 1905,2050 1930,2075 2000,2075 J11.6@2050,2025 2053.5,2021.5 R49.1@2140,2021.5
GPIO7_BP: J8/J6.77 R45.2 | length 1191.5
  Top Signal w5: J8/J6.77@1950,1225 1990,1265 1990,1425 2040,1475 2085,1475 2099.02,1489.02 2099.02,2252.52 2115,2268.5 2115,2298.5 R45.2@2131.5,2315
GPIO7_FSITXCLK: J11.2 R45.1 U1.68 | length 1866.8
  Top Signal w5: U1.68@1372,2722.97 1345.63,2696.6 1345.63,2647.02 1397.65,2595 v1(1570,2595) ; J11.2@2050,2225 2050,2355 2050,2373 cw(c2054.5,2373) 2054.5,2377.5 2090.06,2377.5 ccw(c2090.06,2382) 2094.56,2382 2094.56,2388 ccw(c2090.06,2388) 2090.06,2392.5 2050,2392.5 2034.94,2392.5 cw(c2034.94,2397) 2030.44,2397 2030.44,2403 cw(c2034.94,2403) 2034.94,2407.5 2050,2407.5 2090.06,2407.5 ccw(c2090.06,2412) 2094.56,2412 2094.56,2418 ccw(c2090.06,2418) 2090.06,2422.5 2050,2422.5 2034.94,2422.5 cw(c2034.94,2427) 2030.44,2427 2030.44,2433 cw(c2034.94,2433) 2034.94,2437.5 2050,2437.5 2090.06,2437.5 ccw(c2090.06,2442) 2094.56,2442 2094.56,2448 ccw(c2090.06,2448) 2090.06,2452.5 2050,2452.5 2034.94,2452.5 cw(c2034.94,2457) 2030.44,2457 2030.44,2463 cw(c2034.94,2463) 2034.94,2467.5 2050,2467.5 2090.06,2467.5 ccw(c2090.06,2472) 2094.56,2472 2094.56,2478 ccw(c2090.06,2478) 2090.06,2482.5 2050,2482.5 2034.94,2482.5 cw(c2034.94,2487) 2030.44,2487 2030.44,2493 cw(c2034.94,2493) 2034.94,2497.5 2050,2497.5 2090.06,2497.5 ccw(c2090.06,2502) 2094.56,2502 2094.56,2508 ccw(c2090.06,2508) 2090.06,2512.5 2050,2512.5 2034.94,2512.5 cw(c2034.94,2517) 2030.44,2517 2030.44,2523 cw(c2034.94,2523) 2034.94,2527.5 2050,2527.5 2090.06,2527.5 ccw(c2090.06,2532) 2094.56,2532 2094.56,2538 ccw(c2090.06,2538) 2090.06,2542.5 2054.5,2542.5 cw(c2054.5,2547) 2050,2547 2050,2550 v1(2050,2595)
  Bottom Signal w5: v1(1570,2595) v1(2050,2595)
GPIO8: J4/J2.12 R46.2 U1.58 | length 1740.7
  Top Signal w5: U1.58@1441.59,2487.73 1464.64,2464.69 1549.53,2464.69 v1(1564.21,2450) ; v1(1750,2265) v1(1750,2450) ; J4/J2.12@2050,3225 2120,3155 v1(2120,2450)
  Bottom Signal w5: v1(1564.21,2450) v1(1750,2450) v1(2120,2450) ; v1(1750,2265) 1768.5,2246.5 R46.2@1800,2246.5
GPIO9: J1/J3.7 U1.75 | length 1631.7
  Top Signal w5: U1.75@1274.56,2820.4 1330.24,2876.08 v1(1330.24,3295)
  Bottom Signal w5: J1/J3.7@250,3425 300,3375 950,3375 1030,3295 v1(1330.24,3295)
